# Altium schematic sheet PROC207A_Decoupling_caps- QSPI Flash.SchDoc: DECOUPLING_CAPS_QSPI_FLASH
size 431 x 279 mm; Date: Not shown in title block; ApprovedBy: Not shown in title block; CheckedBy: Not shown in title block; Author: Not shown in title block; CompanyName: Not shown in title block; DrawnBy: Mistral; Engineer: Not shown in title block; Organization: Not shown in title block; Address1: Not shown in title block; Address2: Not shown in title block; Address3: Not shown in title block; Address4: Not shown in title block; DocumentNumber: 2; Revision: Use project parameter SCH_Rev; SheetNumber: 8; SheetTotal: 18; PageSetup: Record=PageOptions¦CenterHorizontal=True¦CenterVertical=True¦PrintScale=1.00¦XCorrection=1.00¦YCorrection=1.00¦PrintKind=0¦BorderSize=5000000¦LeftOffset=0¦BottomOffset=0¦Orientation=2¦PaperLength=1000¦PaperWidth=1000¦Scale=100¦PaperSource=15¦PrintQuality=600¦MediaType=1¦DitherType=10¦PaperKind=Letter¦PrintScaleMode=1
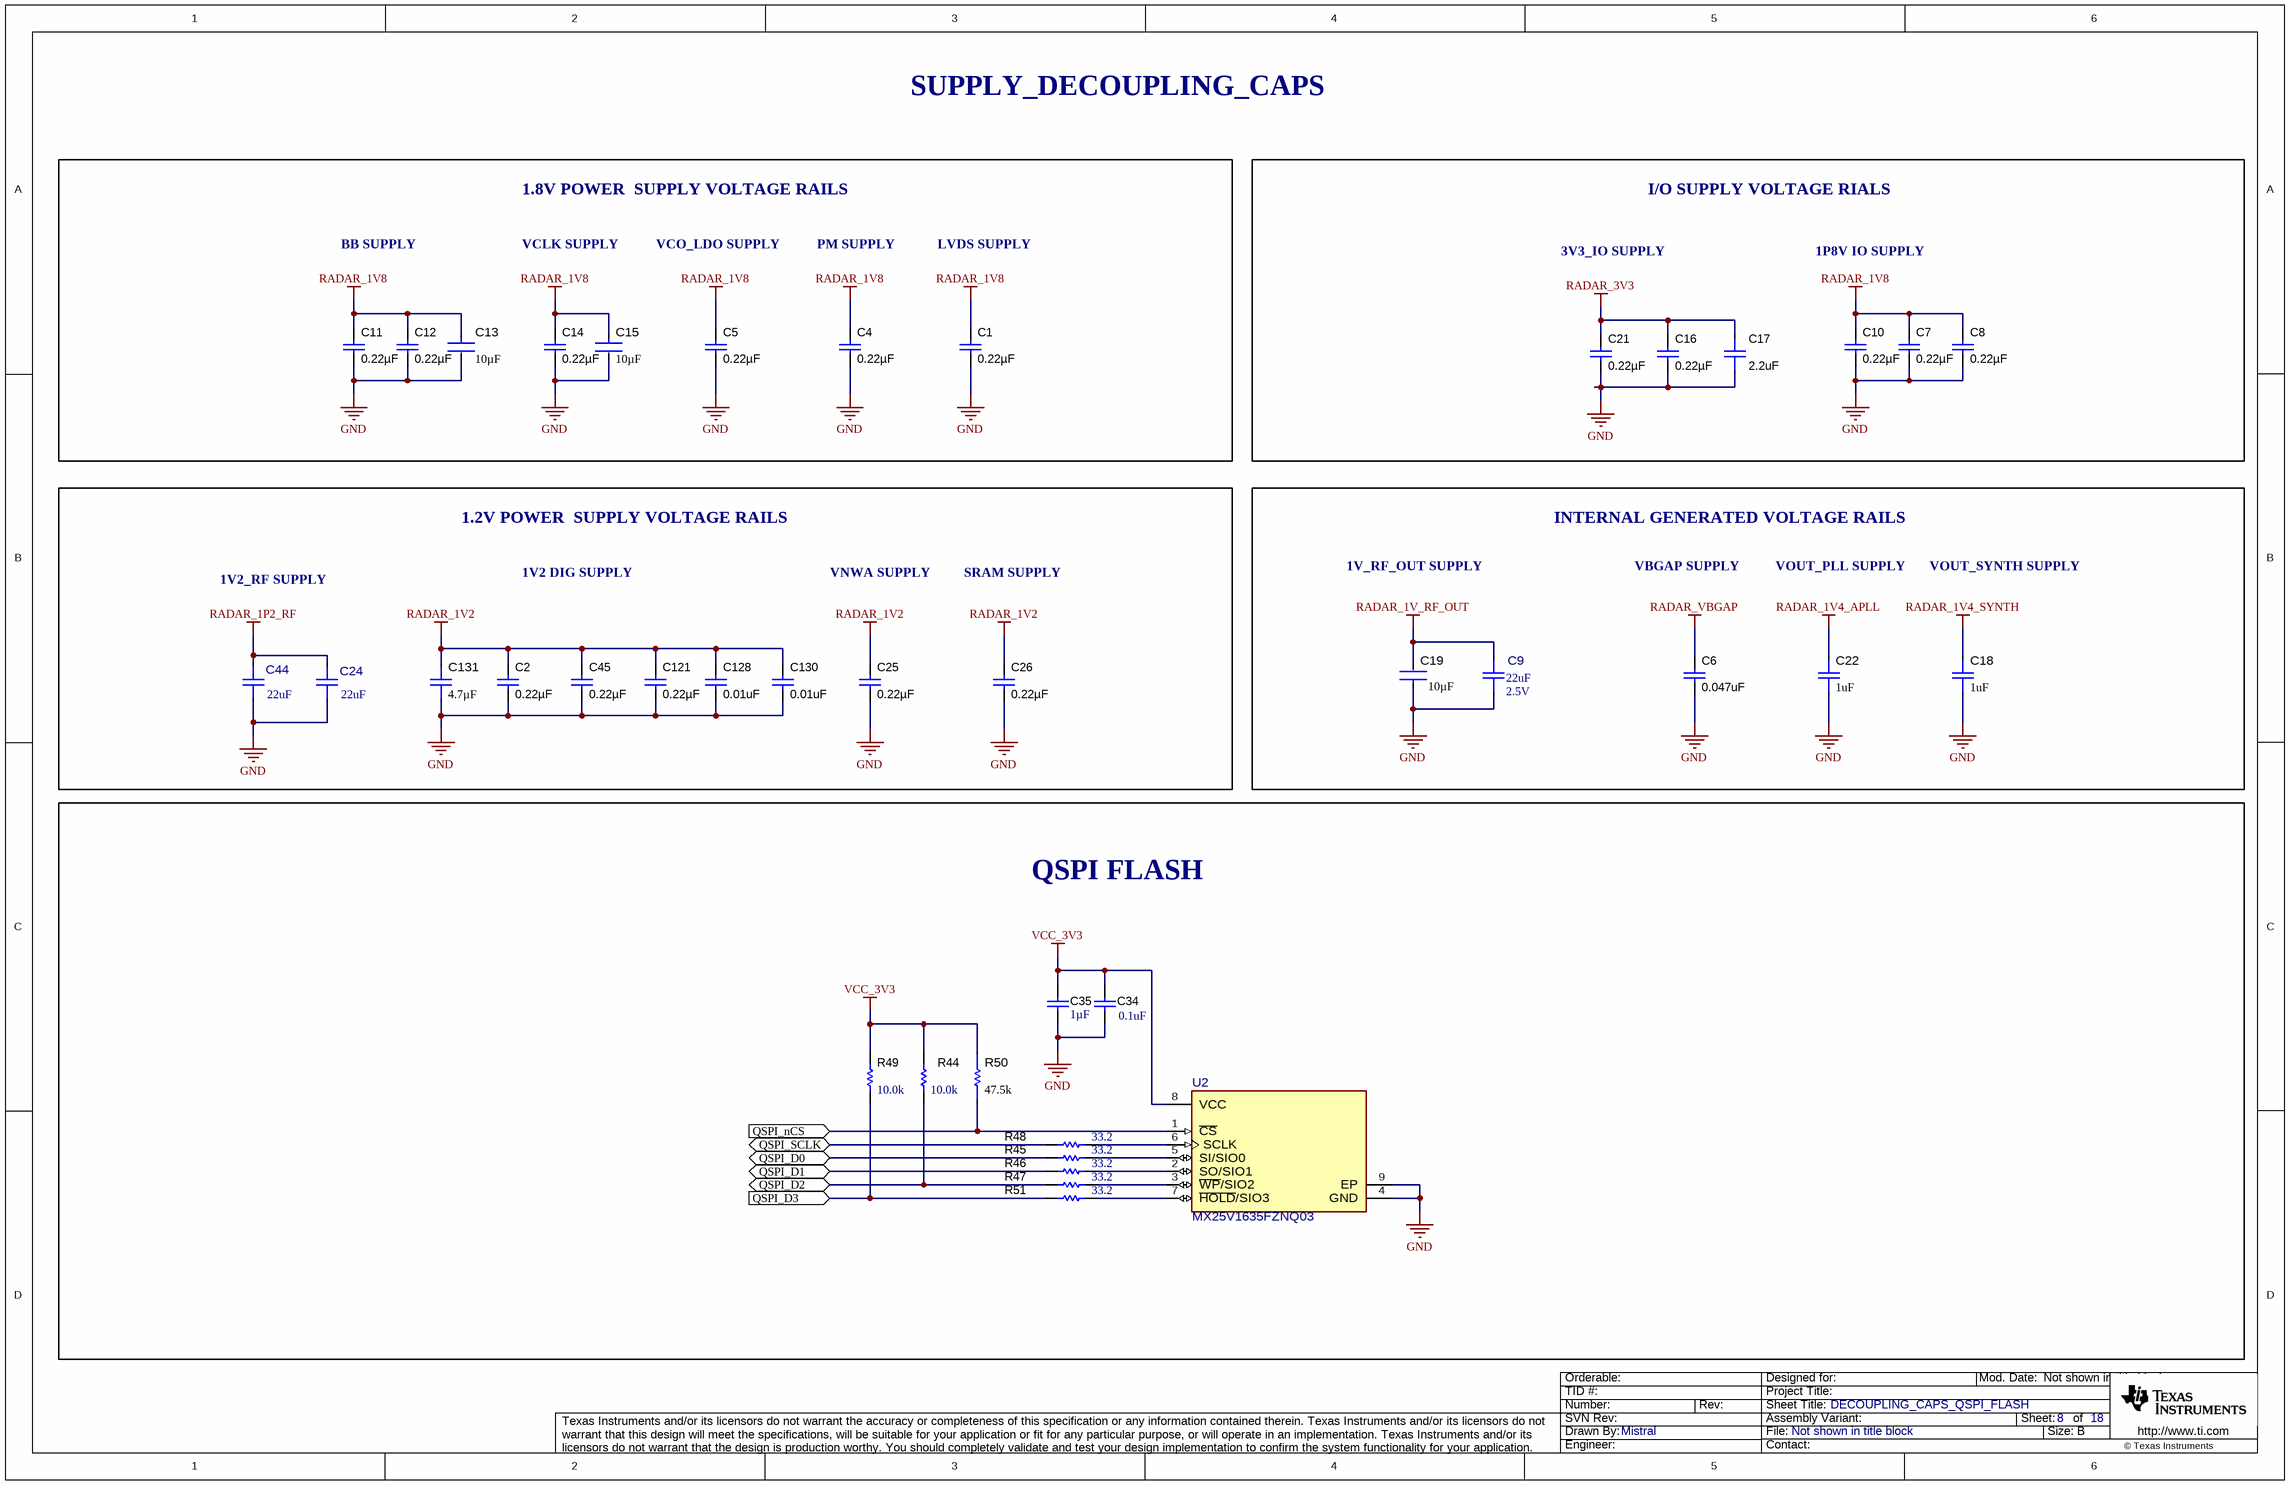
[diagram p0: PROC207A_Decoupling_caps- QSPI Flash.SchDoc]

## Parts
C1  ValueDisplayed: 0.22µF  [0402L]  (hidden comment: GCM155R71C224KE02D)
C2  ValueDisplayed: 0.22µF  [0402L]  (hidden comment: GCM155R71C224KE02D)
C4  ValueDisplayed: 0.22µF  [0402L]  (hidden comment: GCM155R71C224KE02D)
C5  ValueDisplayed: 0.22µF  [0402L]  (hidden comment: GCM155R71C224KE02D)
C6  ValueDisplayed: 0.047uF  [0402L]  (hidden comment: CGA2B3X7R1H473K050BB)
C7  ValueDisplayed: 0.22µF  [0402L]  (hidden comment: GCM155R71C224KE02D)
C8  ValueDisplayed: 0.22µF  [0402L]  (hidden comment: GCM155R71C224KE02D)
C9  ValueDisplayed: 22uF  VDC_V: 2.5V  [FP-GCM188D70E226ME36D_0603-MFG]  (hidden comment: GCM188D70E226ME36D)
C10  ValueDisplayed: 0.22µF  [0402L]  (hidden comment: GCM155R71C224KE02D)
C11  ValueDisplayed: 0.22µF  [0402L]  (hidden comment: GCM155R71C224KE02D)
C12  ValueDisplayed: 0.22µF  [0402L]  (hidden comment: GCM155R71C224KE02D)
C13  Cap_F: 10µF  [FP-GCM188D70J106ME36D_0603-MFG]  (hidden comment: GCM188D70J106ME36D)
C14  ValueDisplayed: 0.22µF  [0402L]  (hidden comment: GCM155R71C224KE02D)
C15  Cap_F: 10µF  [FP-GCM188D70J106ME36D_0603-MFG]  (hidden comment: GCM188D70J106ME36D)
C16  ValueDisplayed: 0.22µF  [0402L]  (hidden comment: GCM155R71C224KE02D)
C17  ValueDisplayed: 2.2uF  [FP-GRT155C71A225KE13D_0402-MFG]  (hidden comment: GRT155C71A225KE13D)
C18  ValueDisplayed: 1uF  [FP-GRT155R70J105KE01D_0402-MFG]  (hidden comment: GRT155R70J105KE01D)
C19  Cap_F: 10µF  [FP-GCM188D70J106ME36D_0603-MFG]  (hidden comment: GCM188D70J106ME36D)
C21  ValueDisplayed: 0.22µF  [0402L]  (hidden comment: GCM155R71C224KE02D)
C22  ValueDisplayed: 1uF  [FP-GRT155R70J105KE01D_0402-MFG]  (hidden comment: GRT155R70J105KE01D)
C24  ValueDisplayed: 22uF  [FP-GCM188D70E226ME36D_0603-MFG]  (hidden comment: GCM188D70E226ME36D)
C25  ValueDisplayed: 0.22µF  [0402L]  (hidden comment: GCM155R71C224KE02D)
C26  ValueDisplayed: 0.22µF  [0402L]  (hidden comment: GCM155R71C224KE02D)
C34  ValueDisplayed: 0.1uF  [0402]  (hidden comment: GCM155R71H104KE02D)
C35  Cap_F: 1µF  [0603]  (hidden comment: CL10B105KA8NNNC)
C44  ValueDisplayed: 22uF  [FP-GCM188D70E226ME36D_0603-MFG]  (hidden comment: GCM188D70E226ME36D)
C45  ValueDisplayed: 0.22µF  [0402L]  (hidden comment: GCM155R71C224KE02D)
C121  ValueDisplayed: 0.22µF  [0402L]  (hidden comment: GCM155R71C224KE02D)
C128  ValueDisplayed: 0.01uF  [0402L]  (hidden comment: GCM155R71E103KA37D)
C130  ValueDisplayed: 0.01uF  [0402L]  (hidden comment: GCM155R71E103KA37D)
C131  Cap_F: 4.7µF  [FP-GCJ21BR71C475KA01L_0805-MFG]  (hidden comment: GCJ21BR71C475KA01L)
R44  value 10.0k  [0402]  (hidden comment: CRCW040210K0FKED)
R45  value 33.2  [0402]  (hidden comment: CRCW040233R2FKED)
R46  value 33.2  [0402]  (hidden comment: CRCW040233R2FKED)
R47  value 33.2  [0402]  (hidden comment: CRCW040233R2FKED)
R48  value 33.2  [0402]  (hidden comment: CRCW040233R2FKED)
R49  value 10.0k  [0402]  (hidden comment: CRCW040210K0FKED)
R50  value 47.5k  [FP-RC0402FR-1047K5L_0402-MFG]  (hidden comment: RC0402FR-1047K5L)
R51  value 33.2  [0402]  (hidden comment: CRCW040233R2FKED)
U2  MX25V1635FZNQ03  [FP-MX25V1635FZNQ03_WSON8-MFG]

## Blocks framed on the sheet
1.8V POWER  SUPPLY VOLTAGE RAILS: C1 C4 C5 C11-C15
I/O SUPPLY VOLTAGE RIALS: C7 C8 C10 C16 C17 C21
1.2V POWER  SUPPLY VOLTAGE RAILS: C2 C24-C26 C44 C45 C121 C128 C130 C131
INTERNAL GENERATED VOLTAGE RAILS: C6 C9 C18 C19 C22
QSPI FLASH: C34 C35 R44-R51 U2

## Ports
QSPI_D0 (bidir), QSPI_D1 (bidir), QSPI_D2 (bidir), QSPI_D3 (in), QSPI_nCS (in), QSPI_SCLK (bidir)

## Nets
GND: C1.1 C2.1 C4.1 C5.1 C6.2 C7.1 C8.1 C9.1 C10.1 C11.1 C12.1 C13.2 C14.1 C15.2 C16.1 C17.1 C18.1 C19.1 C21.1 C22.1 C24.1 C25.1 C26.1 C34.2 C35.1 C44.2 C45.1 C121.1 C128.2 C130.2 C131.1 U2.4(GND) U2.9(EP)
RADAR_1P2_RF: C24.2 C44.1
RADAR_1V2: C2.2 C25.2 C26.2 C45.2 C121.2 C128.1 C130.1 C131.2
RADAR_1V4_APLL: C22.2
RADAR_1V4_SYNTH: C18.2
RADAR_1V8: C1.2 C4.2 C5.2 C7.2 C8.2 C10.2 C11.2 C12.2 C13.1 C14.2 C15.1
RADAR_1V_RF_OUT: C9.2 C19.2
RADAR_3V3: C16.2 C17.2 C21.2
RADAR_VBGAP: C6.1
VCC_3V3: C34.1 C35.2 R44.2 R49.2 R50.1 U2.8(VCC)
QSPI_D0: R45.2 ; port QSPI_D0
QSPI_D1: R46.1 ; port QSPI_D1
QSPI_D2: R44.1 R47.1 ; port QSPI_D2
QSPI_D3: R49.1 R51.2 ; port QSPI_D3
QSPI_nCS: R50.2 U2.1(~{CS}) ; port QSPI_nCS
QSPI_SCLK: R48.2 ; port QSPI_SCLK
NetR45_1: R45.1 U2.5(SI/SIO0)
NetR46_2: R46.2 U2.2(SO/SIO1)
NetR47_2: R47.2 U2.3(~{WP}/SIO2)
NetR48_1: R48.1 U2.6(SCLK)
NetR51_1: R51.1 U2.7(~{HOLD}/SIO3)

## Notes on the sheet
- SUPPLY_DECOUPLING_CAPS
- BB SUPPLY
- VCLK SUPPLY
- VCO_LDO SUPPLY
- PM SUPPLY
- LVDS SUPPLY
- 3V3_IO SUPPLY
- 1P8V IO SUPPLY
- 1V_RF_OUT SUPPLY
- VBGAP SUPPLY
- VOUT_PLL SUPPLY
- VOUT_SYNTH SUPPLY
- 1V2_RF SUPPLY
- 1V2 DIG SUPPLY
- VNWA SUPPLY
- SRAM SUPPLY

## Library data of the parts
C1 C2 C4 C5 C7 C8 C10-C12 C14 C16 C21 C25 C26 C45 C121 = CMP-0078265-1: CAP, CERM, 0.22 µF, 16 V,+/- 10%, X7R, AEC-Q200 Grade 1, 0402; Manufacturer: MuRata; TaMin_C: -55°C; Polarized: N; SizeAreaWB_mm2: 3; U/M: EA; Value: 0.22uF; TaMax_C: 125°C; SizeZ_mm: 0.6; SizeX_mm: 1; SizeY_mm: 0.5; Cap_Case: 0402; Value2: 16V; CompType: Capacitor; AEC Qualified: Y; Cap_F: 220nF; AEC Category: Q200
C6 = CMP-0006330-2: CAP, CERM, 0.047 uF, 50 V, +/- 10%, X7R, AEC-Q200 Grade 1, 0402; Manufacturer: TDK; Polarized: N; U/M: EA; Cap_F: 47nF; ESR_ohm: 0.06407; Value1: 0.06407 ohm; VDC_V: 50V; IRMS_A: 646.122mA; TaMin_C: -55°C; TaMax_C: 125°C; Cap_Case: 0402; SizeArea_mm2: 0.5; SizeAreaWB_mm2: 3; SizeX_mm: 1; SizeZ_mm: 0.6; AEC Category: Q200; AEC Qualified: Y
C9 C24 C44 = CMP-0048366-1: 22 µF ±20% 2.5V Ceramic Capacitor X7T 0603 (1608 Metric); Manufacturer: Murata; AEC Grade: Grade 1; AEC Qualified: Yes; Cap_F: 22µF; SizeZ_mm: 1mm; TempCo: +22/-33%; Value: 22µF
C13 C15 C19 = CMP-0086534-1: Chip Multilayer Ceramic Capacitors for Automotive; Manufacturer: Murata; Tolerance_%: 20%; SizeZ_mm: 1mm; TempCo: -33+22%; Symbol Name: SYM-GCM188D70J106ME36D; VDC_V: 6.3V; AEC Grade: Grade 1; AEC Qualified: Yes
C17 = CMP-0094968-1: Multi-Layer Ceramic Capacitor 2.2uF 10V X7S ±10% 0402 Paper T/R; Manufacturer: Murata; AEC Grade: Grade 1; Cap_F: 2.2µF; SizeZ_mm: 0.7mm; Value: 2.2µF; AEC Qualified: Yes; TempCo: 22%
C18 C22 = CMP-0088425-1: 1µF ±10% 6.3V Ceramic Capacitor X7R 0402 (1005 Metric); Manufacturer: Murata; AEC Grade: Grade 1; SizeZ_mm: 0.55mm; AEC Qualified: Yes; TempCo: 15%
C34 = CMP-0006356-2: CAP, CERM, 0.1 uF, 50 V, +/- 10%, X7R, AEC-Q200 Grade 1, 0402; Manufacturer: MuRata; TaMin_C: -55°C; Polarized: N; SizeAreaWB_mm2: 3; Value1: Unknown; U/M: EA; Value: 0.1uF; TaMax_C: 125°C; SizeZ_mm: 0.6; SizeX_mm: 1; SizeY_mm: 0.5; Value2: 50V; AEC Qualified: Y; Cap_F: 100nF; AEC Category: Q200
C35 = CMP-0086540-3: CAP, 1uF, 25V, ±10%, X7R, 0603; Manufacturer: Samsung; SizeZ_mm: 0.9mm; AEC Qualified: No; TempCo: 15%; Symbol Name: SYM-CL10B105KA8NNNC
C128 C130 = CMP-0006352-2: CAP, CERM, 0.01 uF, 25 V, +/- 10%, X7R, 0402; Manufacturer: MuRata; TaMin_C: -55°C; Polarized: N; SizeAreaWB_mm2: 3; Value1: Unknown; U/M: EA; Value: 0.01uF; TaMax_C: 125°C; SizeZ_mm: 0.6; SizeX_mm: 1; SizeY_mm: 0.5; Cap_Case: 0402; Value2: 25V; CompType: Capacitor; Cap_F: 10nF; AEC Category: Q200
C131 = CMP-0094778-1: Multilayer Ceramic Capacitors MLCC - SMD/SMT 0805 4.7uF 10%, 16VDC,  X7R 15%; Manufacturer: Murata; AEC Qualified: Yes; Value: 4.7µF; AEC Grade: Grade 1; SizeZ_mm: 1.45mm; VDC_V: 16V
R44 R49 = CMP-0025958-3: RES, 10.0 k, 1%, 0.063 W, AEC-Q200 Grade 0, 0402; Manufacturer: Vishay-Dale; AEC Qualified: Y; Power_W: 63mW; Res_ohm: 10k; SizeZ_mm: 0.6; TempCo: 100 ppm/C; VDC_V: 50V; AEC Category: Q200; AEC Grade: 0; EIA_Code: E96; SizeArea_mm2: 0.5; SizeX_mm: 1; Value2: 0.063W; Value_Code: 10k0
R45-R48 R51 = CMP-0026299-2: RES, 33.2, 1%, 0.063 W, AEC-Q200 Grade 0, 0402; Manufacturer: Vishay-Dale; AEC Qualified: Y; Power_W: 63mW; SizeZ_mm: 0.6; TempCo: 100 ppm/C; VDC_V: 50V; AEC Category: Q200; AEC Grade: 0; EIA_Code: E96; SizeArea_mm2: 0.5; SizeX_mm: 1; Value2: 0.063W; Value_Code: 33R2
R50 = CMP-0120015-1: General Purpose Chip Resistor Thick Film 0402 47.5kOhm 1% Paper T/R; Manufacturer: YAGEO; AEC Qualified: No; Power_W: 63mW; SizeZ_mm: 0.4mm; TempCo: 100ppm/°C; VDC_V: 50V
U2 = CMP-0093403-2: NOR Flash 16Mbit 16M x 1/8M x 2/4M x 4 Serial-SPI 3.3V 8-Pin WSON; Manufacturer: Macronix; TaMax_C: +85°C; AEC Qualified: No; Interface: SPI; Max Supply Voltage: 3.6V; TaMin_C: -40°C; Min Supply Voltage: 2.3V; Memory Type: FLASH,NOR; SizeZ_mm: 0.8mm; Memory Size: 16Mbits; Frequency_Fixed: 80MHz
